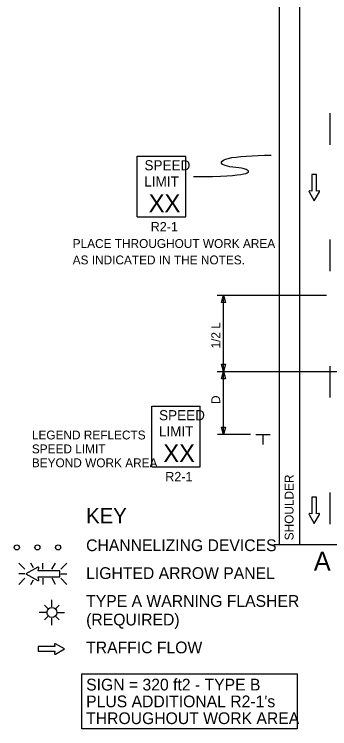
# Model space of a CAD drawing. Extents: x 16738 to 19504, y 5697 to 6916.
# Drawn here: x 16738 to 16987, y 5968 to 6533 of the extents above; entities that cross this region are included whole.
import ezdxf

# ---------------------------------------------------------------- set-up
doc = ezdxf.new("R2010")
doc.units = 0
for name, color, linetype in [('ALI_LEGAL_EX', 7, 'Continuous'), ('MT_SCRATCH_LEVEL_E', 7, 'Continuous'), ('PAVT_EDGE_EX', 7, 'Continuous'), ('TRAFFIC_SIGNS_PR', 7, 'Continuous'), ('TYPICAL_TEXT_DIMEN_EX', 7, 'Continuous'), ('TYPICAL_TEXT_DIMEN_PR', 7, 'Continuous')]:
    doc.layers.add(name, color=color, linetype=linetype)

msp = doc.modelspace()

# ---------------------------------------------------------------- linework, layer by layer
at = {"layer": 'ALI_LEGAL_EX'}
for points in [[(16987.43, 6454.77), (16987.43, 6429.77)], [(16987.43, 6354.77), (16987.43, 6329.77)], [(16987.43, 6254.77), (16987.43, 6229.77)], [(16987.43, 6154.77), (16987.43, 6129.77)]]:
    msp.add_lwpolyline(points, dxfattribs=at)
at = {"layer": 'MT_SCRATCH_LEVEL_E'}
for p, q in [((16977.1, 6406.32), (16973.36, 6406.32)), ((16973.36, 6406.32), (16973.36, 6393.06)), ((16977.1, 6406.32), (16973.36, 6406.32)), ((16973.36, 6406.32), (16973.36, 6393.06)), ((16977.1, 6393.06), (16977.1, 6406.32)), ((16977.1, 6393.06), (16977.1, 6406.32)), ((16973.36, 6393.06), (16971.58, 6393.37)), ((16973.36, 6393.06), (16971.58, 6393.37)), ((16978.88, 6393.37), (16977.1, 6393.06)), ((16978.88, 6393.37), (16977.1, 6393.06)), ((16971.1, 6392.69), (16975.25, 6385.45)), ((16971.1, 6392.69), (16975.25, 6385.45)), ((16975.25, 6385.45), (16979.36, 6392.69)), ((16975.25, 6385.45), (16979.36, 6392.69)), ((16977.1, 6151.05), (16973.36, 6151.05)), ((16973.36, 6151.05), (16973.36, 6137.79)), ((16977.1, 6151.05), (16973.36, 6151.05)), ((16973.36, 6151.05), (16973.36, 6137.79)), ((16977.1, 6137.79), (16977.1, 6151.05)), ((16977.1, 6137.79), (16977.1, 6151.05)), ((16971.1, 6137.42), (16975.25, 6130.18)), ((16971.1, 6137.42), (16975.25, 6130.18)), ((16973.36, 6137.79), (16971.58, 6138.11)), ((16973.36, 6137.79), (16971.58, 6138.11)), ((16975.25, 6130.18), (16979.36, 6137.42)), ((16975.25, 6130.18), (16979.36, 6137.42)), ((16978.88, 6138.11), (16977.1, 6137.79)), ((16978.88, 6138.11), (16977.1, 6137.79)), ((16770.11, 6032.83), (16756.85, 6032.83)), ((16756.85, 6032.83), (16756.85, 6029.09)), ((16770.11, 6032.83), (16756.85, 6032.83)), ((16756.85, 6032.83), (16756.85, 6029.09)), ((16769.79, 6034.61), (16770.11, 6032.83)), ((16769.79, 6034.61), (16770.11, 6032.83)), ((16777.72, 6030.98), (16770.48, 6035.09)), ((16777.72, 6030.98), (16770.48, 6035.09)), ((16756.85, 6029.09), (16770.11, 6029.09)), ((16756.85, 6029.09), (16770.11, 6029.09)), ((16770.11, 6029.09), (16769.79, 6027.31)), ((16770.11, 6029.09), (16769.79, 6027.31)), ((16770.48, 6026.83), (16777.72, 6030.98)), ((16770.48, 6026.83), (16777.72, 6030.98))]:
    msp.add_line(p, q, dxfattribs=at)
for centre, start, end in [((16971.51, 6392.91), 80.0362, 209.7731), ((16971.51, 6392.91), 80.0362, 209.7731), ((16978.96, 6392.91), 330.4248, 99.9638), ((16978.96, 6392.91), 330.4248, 99.9638), ((16971.51, 6137.65), 80.0362, 209.7731), ((16971.51, 6137.65), 80.0362, 209.7731), ((16978.96, 6137.65), 330.4248, 99.9638), ((16978.96, 6137.65), 330.4248, 99.9638), ((16770.25, 6034.68), 60.4248, 189.9638), ((16770.25, 6034.68), 60.4248, 189.9638), ((16770.25, 6027.24), 170.0362, 299.7731), ((16770.25, 6027.24), 170.0362, 299.7731)]:
    msp.add_arc(centre, 0.463, start, end, dxfattribs=at)
at = {"layer": 'PAVT_EDGE_EX'}
for p, q in [((16947.43, 6911.29), (16947.43, 6113.54)), ((16963.43, 6911.29), (16963.43, 6113.54))]:
    msp.add_line(p, q, dxfattribs=at)
at = {"layer": 'TRAFFIC_SIGNS_PR'}
for p, q in [((16835.12, 6420.74), (16873.52, 6420.74)), ((16835.12, 6372.74), (16835.12, 6420.74)), ((16873.52, 6372.74), (16873.52, 6420.74)), ((16835.12, 6372.74), (16873.52, 6372.74)), ((16846.67, 6223), (16885.07, 6223)), ((16846.67, 6175), (16846.67, 6223)), ((16885.07, 6175), (16885.07, 6223)), ((16846.67, 6175), (16885.07, 6175)), ((16741.4, 6098.92), (16746.33, 6093.99)), ((16753.16, 6095.1), (16750.95, 6098.92)), ((16760.48, 6093.99), (16760.48, 6098.92)), ((16767.72, 6093.99), (16770.57, 6098.92)), ((16774.63, 6093.99), (16779.57, 6098.92)), ((16746.33, 6090.43), (16741.4, 6090.43)), ((16774.63, 6090.43), (16779.57, 6090.43)), ((16741.4, 6081.94), (16746.33, 6086.87)), ((16750.91, 6081.94), (16753.02, 6085.6)), ((16760.48, 6086.87), (16760.48, 6081.94)), ((16770.61, 6081.94), (16767.76, 6086.87)), ((16774.63, 6086.87), (16779.57, 6081.94)), ((16764.55, 6062.97), (16761.92, 6065.6)), ((16767.68, 6064.27), (16767.68, 6069.89)), ((16770.82, 6062.97), (16773.45, 6065.6)), ((16763.75, 6059.83), (16757.71, 6059.83)), ((16771.62, 6059.83), (16777.72, 6059.83)), ((16764.55, 6056.69), (16761.92, 6054.06)), ((16767.68, 6049.88), (16767.68, 6055.39)), ((16770.82, 6056.69), (16773.45, 6054.06))]:
    msp.add_line(p, q, dxfattribs=at)
for points in [[(16756.41, 6095.71), (16747.12, 6090.43), (16756.41, 6085.11)], [(16757.28, 6085.74), (16756.88, 6088), (16773.9, 6088), (16773.9, 6092.81), (16756.88, 6092.81), (16757.29, 6095.09)]]:
    msp.add_lwpolyline(points, dxfattribs=at)
for centre, radius in [((16739.91, 6111.27), 2), ((16756.21, 6111.27), 2), ((16772.51, 6111.27), 2), ((16767.68, 6059.83), 3.94)]:
    msp.add_circle(centre, radius, dxfattribs=at)
for centre, radius, start, end in [((16756.7, 6095.18), 0.598, 350.7308, 118.8916), ((16756.69, 6085.63), 0.597, 241.4833, 9.9593)]:
    msp.add_arc(centre, radius, start, end, dxfattribs=at)
at = {"layer": 'TYPICAL_TEXT_DIMEN_EX'}
msp.add_lwpolyline([(16791.41, 6011.2), (16961.8, 6011.2), (16961.8, 5967.83), (16791.41, 5967.83)], close=True, dxfattribs=at)
at = {"layer": 'TYPICAL_TEXT_DIMEN_PR'}
for p, q in [((16898.34, 6310.95), (16984.84, 6310.95)), ((16901.77, 6305.09), (16903.34, 6310.95)), ((16903.34, 6250.52), (16903.34, 6310.95)), ((16903.34, 6310.95), (16904.91, 6305.09)), ((16903.34, 6305.09), (16901.77, 6305.09)), ((16904.91, 6305.09), (16903.34, 6305.09)), ((16903.34, 6250.52), (16901.77, 6256.38)), ((16901.77, 6256.38), (16903.34, 6256.38)), ((16903.34, 6256.38), (16904.91, 6256.38)), ((16904.91, 6256.38), (16903.34, 6250.52)), ((16898.34, 6250.52), (17027.97, 6250.52)), ((16901.77, 6244.65), (16903.34, 6250.52)), ((16903.34, 6200.52), (16903.34, 6250.52)), ((16903.34, 6250.52), (16904.91, 6244.65)), ((16903.34, 6244.65), (16901.77, 6244.65)), ((16904.91, 6244.65), (16903.34, 6244.65)), ((16903.34, 6200.52), (16901.77, 6206.38)), ((16901.77, 6206.38), (16903.34, 6206.38)), ((16903.34, 6206.38), (16904.91, 6206.38)), ((16904.91, 6206.38), (16903.34, 6200.52)), ((16924.7, 6200.52), (16898.7, 6200.52)), ((16928.95, 6200.52), (16940.2, 6200.52)), ((16934.58, 6200.52), (16934.58, 6192.73)), ((16943.13, 6113.54), (17103.73, 6113.54))]:
    msp.add_line(p, q, dxfattribs=at)
msp.add_open_spline([(16879.58, 6404.69), (16925.67, 6404.69), (16925.67, 6411.96), (16900.5, 6411.96), (16900.5, 6420.1), (16927.15, 6421.39), (16941.2, 6421.61)], degree=3, dxfattribs=at)

# ---------------------------------------------------------------- texts
at = {"layer": 'TRAFFIC_SIGNS_PR'}
for s, height, p in [('SPEED', 8, (16840.89, 6409.61)), ('LIMIT', 8, (16840.73, 6396.81)), ('XX', 14.031, (16844.23, 6376.5)), ('R2-1', 7.44, (16845.8, 6361.3)), ('PLACE THROUGHOUT WORK AREA', 7, (16784.11, 6348.2)), ('AS INDICATED IN THE NOTES.', 7, (16784.11, 6335.2)), ('SPEED', 8, (16852.44, 6211.86)), ('LIMIT', 8, (16852.28, 6199.06)), ('XX', 14.031, (16855.78, 6178.76)), ('R2-1', 7.44, (16857.35, 6163.56))]:
    msp.add_text(s, height=height, dxfattribs=at).set_placement(p)
at = {"layer": 'TYPICAL_TEXT_DIMEN_EX'}
for s, height, p in [('KEY', 12, (16794.75, 6130.38)), ('CHANNELIZING DEVICES', 9.3, (16794.75, 6108.33)), ('LIGHTED ARROW PANEL', 9.3, (16794.75, 6086.28)), ('TYPE A WARNING FLASHER', 9.3, (16794.75, 6064.23)), ('(REQUIRED)', 9.3, (16794.75, 6049.53)), ('TRAFFIC FLOW', 9.3, (16794.75, 6027.48)), ('SIGN = 320 ft2 - TYPE B', 9.3, (16794.75, 5998.08)), ("PLUS ADDITIONAL R2-1's", 9.3, (16794.75, 5984.78)), ('THROUGHOUT WORK AREA', 9.3, (16794.75, 5971.48))]:
    msp.add_text(s, height=height, dxfattribs=at).set_placement(p)
at = {"layer": 'TYPICAL_TEXT_DIMEN_PR'}
for s, p in [('1/2 L', (16900.78, 6268.67)), ('D', (16900.78, 6224.73)), ('SHOULDER', (16958.81, 6116.92))]:
    msp.add_text(s, height=7, rotation=90, dxfattribs=at).set_placement(p)
for s, height, p in [('LEGEND REFLECTS', 7, (16751.81, 6196.7)), ('SPEED LIMIT', 7, (16751.81, 6185.7)), ('BEYOND WORK AREA', 7, (16751.81, 6174.7)), ('A MATCH A', 15, (16974.85, 6092.84))]:
    msp.add_text(s, height=height, dxfattribs=at).set_placement(p)

doc.saveas('drawing.dxf')
